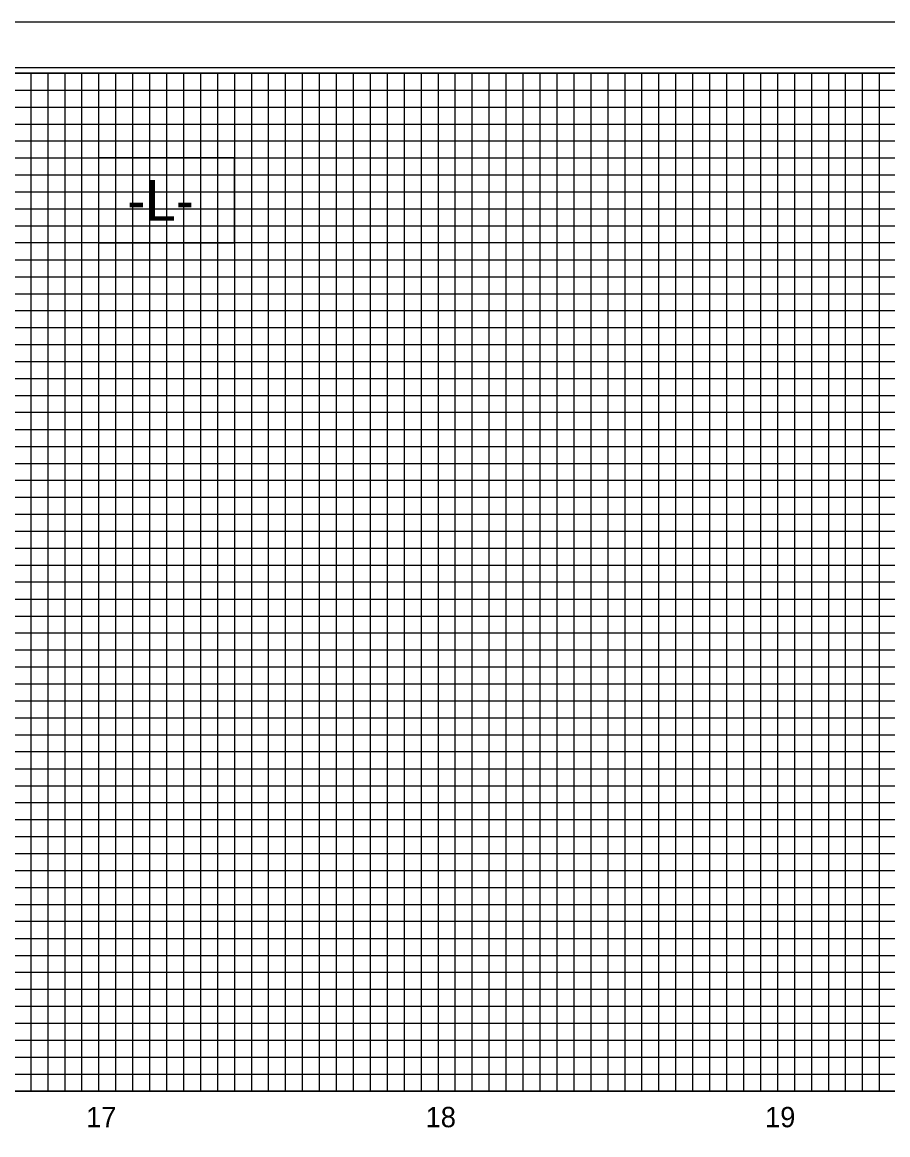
# Model space of a CAD drawing. Extents: x 2113883 to 2114903, y 714180 to 714840.
# Drawn here: x 2114390.3 to 2114645.3, y 714512.4 to 714840.3 of the extents above; entities that cross this region are included whole.
import ezdxf

# ---------------------------------------------------------------- set-up
doc = ezdxf.new("R2010")
doc.units = 0
for name, color, linetype in [('Exist Vertical Profile Horizontal Axis Label Major', 7, 'Continuous'), ('Prop Grid Mask', 7, 'Continuous'), ('Prop PFL Text', 7, 'Continuous'), ('Sheet Cutting Line CELL', 7, 'Continuous'), ('Sheet Layout Profile Border Port 1', 7, 'Continuous'), ('Sheet Plot Border Inside CELL', 7, 'Continuous'), ('Sheet Plot Border Outside CELL', 7, 'Continuous'), ('Sheet Profile CELL', 7, 'Continuous'), ('Sheet Profile Grid Major CELL', 7, 'Continuous'), ('Sheet Profile Grid Middle CELL', 7, 'Continuous'), ('Sheet Profile Grid Minor CELL', 7, 'Continuous')]:
    doc.layers.add(name, color=color, linetype=linetype)

msp = doc.modelspace()

# ---------------------------------------------------------------- linework, layer by layer
at = {"layer": 'Prop Grid Mask'}
msp.add_lwpolyline([(2114412.76, 714775.29), (2114452.76, 714775.29), (2114452.76, 714800.29), (2114412.76, 714800.29)], close=True, dxfattribs=at)
at = {"layer": 'Prop PFL Text'}
msp.add_lwpolyline([(2114412.76, 714775.29), (2114452.76, 714775.29), (2114452.76, 714800.29), (2114412.76, 714800.29)], close=True, dxfattribs=at)
at = {"layer": 'Sheet Cutting Line CELL'}
msp.add_line((2114902.56, 714840.29), (2113882.56, 714840.29), dxfattribs=at)
at = {"layer": 'Sheet Layout Profile Border Port 1'}
msp.add_lwpolyline([(2114012.76, 714825.29), (2114762.73, 714825.29), (2114762.73, 714705.41), (2114852.76, 714705.29), (2114852.76, 714525.29), (2114012.76, 714525.29)], close=True, dxfattribs=at)
at = {"layer": 'Sheet Plot Border Inside CELL'}
msp.add_lwpolyline([(2113890.36, 714193.76), (2114890.26, 714193.76), (2114890.26, 714826.82), (2113890.36, 714826.82)], close=True, dxfattribs=at)
at = {"layer": 'Sheet Plot Border Outside CELL'}
msp.add_lwpolyline([(2113882.56, 714180.29), (2114902.56, 714180.29), (2114902.56, 714840.29), (2113882.56, 714840.29)], close=True, dxfattribs=at)
at = {"layer": 'Sheet Profile CELL'}
msp.add_line((2113982.76, 714525.29), (2114882.76, 714525.29), dxfattribs=at)
msp.add_lwpolyline([(2114882.76, 714825.29), (2113982.76, 714825.29), (2113982.76, 714195.29), (2114882.76, 714195.29)], close=True, dxfattribs=at)
at = {"layer": 'Sheet Profile Grid Major CELL'}
for p, q in [((2114412.76, 714825.29), (2114412.76, 714525.29)), ((2114437.76, 714825.29), (2114437.76, 714525.29)), ((2114462.76, 714825.29), (2114462.76, 714525.29)), ((2114487.76, 714825.29), (2114487.76, 714525.29)), ((2114512.76, 714825.29), (2114512.76, 714525.29)), ((2114537.76, 714825.29), (2114537.76, 714525.29)), ((2114562.76, 714825.29), (2114562.76, 714525.29)), ((2114587.76, 714825.29), (2114587.76, 714525.29)), ((2114612.76, 714825.29), (2114612.76, 714525.29)), ((2114637.76, 714825.29), (2114637.76, 714525.29)), ((2113982.76, 714800.29), (2114762.76, 714800.29)), ((2114762.76, 714775.29), (2113982.76, 714775.29)), ((2113982.76, 714750.29), (2114762.76, 714750.29)), ((2114762.76, 714725.29), (2113982.76, 714725.29)), ((2113982.76, 714700.29), (2114882.76, 714700.29)), ((2114882.76, 714675.29), (2113982.76, 714675.29)), ((2113982.76, 714650.29), (2114882.76, 714650.29)), ((2114882.76, 714625.29), (2113982.76, 714625.29)), ((2113982.76, 714600.29), (2114882.76, 714600.29)), ((2114882.76, 714575.29), (2113982.76, 714575.29)), ((2113982.76, 714550.29), (2114882.76, 714550.29))]:
    msp.add_line(p, q, dxfattribs=at)
at = {"layer": 'Sheet Profile Grid Middle CELL'}
for p, q in [((2114012.76, 714820.29), (2114762.76, 714820.29)), ((2114012.76, 714815.29), (2114762.76, 714815.29)), ((2114012.76, 714810.29), (2114762.76, 714810.29)), ((2114012.76, 714805.29), (2114762.76, 714805.29)), ((2114012.76, 714795.29), (2114762.76, 714795.29)), ((2114012.76, 714790.29), (2114762.76, 714790.29)), ((2114012.76, 714785.29), (2114762.76, 714785.29)), ((2114012.76, 714780.29), (2114762.76, 714780.29)), ((2114012.76, 714770.29), (2114762.76, 714770.29)), ((2114012.76, 714765.29), (2114762.76, 714765.29)), ((2114012.76, 714760.29), (2114762.76, 714760.29)), ((2114012.76, 714755.29), (2114762.76, 714755.29)), ((2114012.76, 714745.29), (2114762.76, 714745.29)), ((2114012.76, 714740.29), (2114762.76, 714740.29)), ((2114012.76, 714735.29), (2114762.76, 714735.29)), ((2114012.76, 714730.29), (2114762.76, 714730.29)), ((2114012.76, 714720.29), (2114762.76, 714720.29)), ((2114012.76, 714715.29), (2114762.76, 714715.29)), ((2114012.76, 714710.29), (2114762.76, 714710.29)), ((2114012.76, 714705.29), (2114852.76, 714705.29)), ((2114012.76, 714695.29), (2114852.76, 714695.29)), ((2114012.76, 714690.29), (2114852.76, 714690.29)), ((2114012.76, 714685.29), (2114852.76, 714685.29)), ((2114012.76, 714680.29), (2114852.76, 714680.29)), ((2114012.76, 714670.29), (2114852.76, 714670.29)), ((2114012.76, 714665.29), (2114852.76, 714665.29)), ((2114012.76, 714660.29), (2114852.76, 714660.29)), ((2114012.76, 714655.29), (2114852.76, 714655.29)), ((2114012.76, 714645.29), (2114852.76, 714645.29)), ((2114012.76, 714640.29), (2114852.76, 714640.29)), ((2114012.76, 714635.29), (2114852.76, 714635.29)), ((2114012.76, 714630.29), (2114852.76, 714630.29)), ((2114012.76, 714620.29), (2114852.76, 714620.29)), ((2114012.76, 714615.29), (2114852.76, 714615.29)), ((2114012.76, 714610.29), (2114852.76, 714610.29)), ((2114012.76, 714605.29), (2114852.76, 714605.29)), ((2114012.76, 714595.29), (2114852.76, 714595.29)), ((2114012.76, 714590.29), (2114852.76, 714590.29)), ((2114012.76, 714585.29), (2114852.76, 714585.29)), ((2114012.76, 714580.29), (2114852.76, 714580.29)), ((2114012.76, 714570.29), (2114852.76, 714570.29)), ((2114012.76, 714565.29), (2114852.76, 714565.29)), ((2114012.76, 714560.29), (2114852.76, 714560.29)), ((2114012.76, 714555.29), (2114852.76, 714555.29)), ((2114012.76, 714545.29), (2114852.76, 714545.29)), ((2114012.76, 714540.29), (2114852.76, 714540.29)), ((2114012.76, 714535.29), (2114852.76, 714535.29)), ((2114012.76, 714530.29), (2114852.76, 714530.29))]:
    msp.add_line(p, q, dxfattribs=at)
at = {"layer": 'Sheet Profile Grid Minor CELL'}
for p, q in [((2114392.76, 714825.29), (2114392.76, 714525.29)), ((2114397.76, 714825.29), (2114397.76, 714525.29)), ((2114402.76, 714825.29), (2114402.76, 714525.29)), ((2114407.76, 714825.29), (2114407.76, 714525.29)), ((2114417.76, 714825.29), (2114417.76, 714525.29)), ((2114422.76, 714825.29), (2114422.76, 714525.29)), ((2114427.76, 714825.29), (2114427.76, 714525.29)), ((2114432.76, 714825.29), (2114432.76, 714525.29)), ((2114442.76, 714825.29), (2114442.76, 714525.29)), ((2114447.76, 714825.29), (2114447.76, 714525.29)), ((2114452.76, 714825.29), (2114452.76, 714525.29)), ((2114457.76, 714825.29), (2114457.76, 714525.29)), ((2114467.76, 714825.29), (2114467.76, 714525.29)), ((2114472.76, 714825.29), (2114472.76, 714525.29)), ((2114477.76, 714825.29), (2114477.76, 714525.29)), ((2114482.76, 714825.29), (2114482.76, 714525.29)), ((2114492.76, 714825.29), (2114492.76, 714525.29)), ((2114497.76, 714825.29), (2114497.76, 714525.29)), ((2114502.76, 714825.29), (2114502.76, 714525.29)), ((2114507.76, 714825.29), (2114507.76, 714525.29)), ((2114517.76, 714825.29), (2114517.76, 714525.29)), ((2114522.76, 714825.29), (2114522.76, 714525.29)), ((2114527.76, 714825.29), (2114527.76, 714525.29)), ((2114532.76, 714825.29), (2114532.76, 714525.29)), ((2114542.76, 714825.29), (2114542.76, 714525.29)), ((2114547.76, 714825.29), (2114547.76, 714525.29)), ((2114552.76, 714825.29), (2114552.76, 714525.29)), ((2114557.76, 714825.29), (2114557.76, 714525.29)), ((2114567.76, 714825.29), (2114567.76, 714525.29)), ((2114572.76, 714825.29), (2114572.76, 714525.29)), ((2114577.76, 714825.29), (2114577.76, 714525.29)), ((2114582.76, 714825.29), (2114582.76, 714525.29)), ((2114592.76, 714825.29), (2114592.76, 714525.29)), ((2114597.76, 714825.29), (2114597.76, 714525.29)), ((2114602.76, 714825.29), (2114602.76, 714525.29)), ((2114607.76, 714825.29), (2114607.76, 714525.29)), ((2114617.76, 714825.29), (2114617.76, 714525.29)), ((2114622.76, 714825.29), (2114622.76, 714525.29)), ((2114627.76, 714825.29), (2114627.76, 714525.29)), ((2114632.76, 714825.29), (2114632.76, 714525.29)), ((2114642.76, 714825.29), (2114642.76, 714525.29))]:
    msp.add_line(p, q, dxfattribs=at)

# ---------------------------------------------------------------- texts
at = {"layer": 'Exist Vertical Profile Horizontal Axis Label Major'}
for s, p in [('17', (2114409.08, 714514.63)), ('17', (2114409.08, 714514.63)), ('17', (2114409.08, 714514.63)), ('18', (2114509.11, 714514.63)), ('18', (2114509.11, 714514.63)), ('18', (2114509.11, 714514.63)), ('19', (2114609.12, 714514.63)), ('19', (2114609.12, 714514.63)), ('19', (2114609.12, 714514.63)), ('19', (2114609.12, 714514.63))]:
    msp.add_text(s, height=6, dxfattribs=at).set_placement(p)
at = {"layer": 'Prop PFL Text'}
msp.add_text('-L-', height=12, dxfattribs=at).set_placement((2114421.22, 714781.79))

doc.saveas('drawing.dxf')
